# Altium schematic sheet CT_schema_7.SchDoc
size 277 x 170 mm
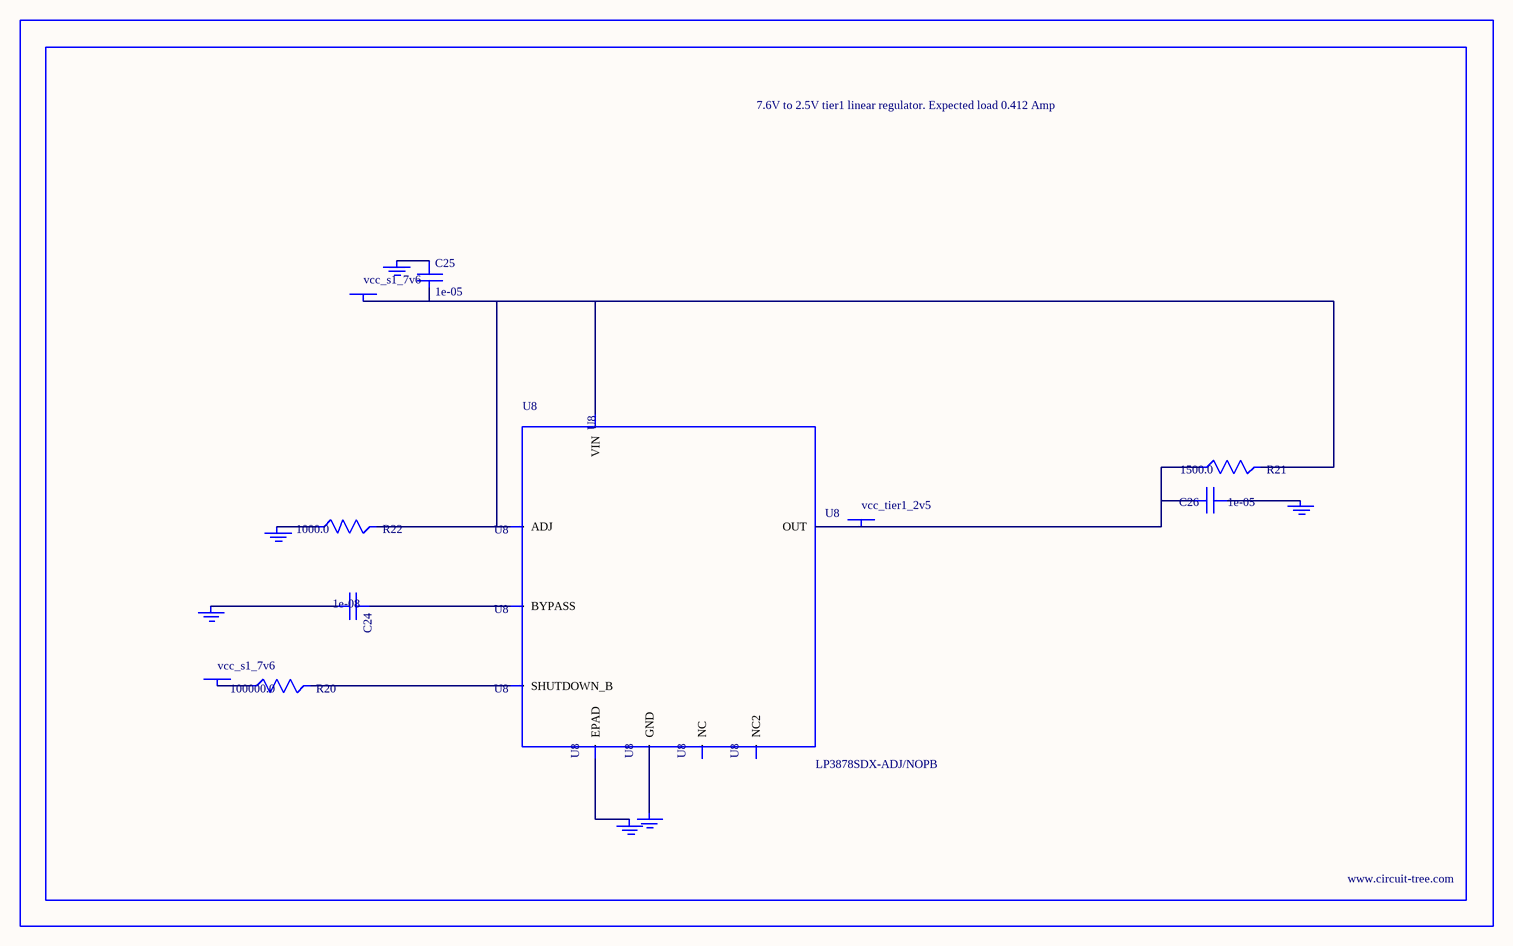
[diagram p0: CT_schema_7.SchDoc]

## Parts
BORDER6  (no value)
C24  1e-08  [C0402]
C25  1e-05  [C1206]
C26  1e-05  [C1210]
GND_INSTANCE_6_0  (no value)
GND_INSTANCE_6_1  (no value)
GND_INSTANCE_6_2  (no value)
GND_INSTANCE_6_3  (no value)
GND_INSTANCE_6_4  (no value)
GND_INSTANCE_6_5  (no value)
POWER_INSTANCE_6_0  vcc_s1_7v6
POWER_INSTANCE_6_1  vcc_s1_7v6
POWER_INSTANCE_6_2  vcc_tier1_2v5
R20  100000.0  [R0603]
R21  1500.0  [R0603]
R22  1000.0  [R0603]
U8  LP3878SDX-ADJ/NOPB  [WSON-8]

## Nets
NetC24_1: C24.1 U8.1(BYPASS)
NetC24_2: C24.2 GND_INSTANCE_6_0.0(GND)
NetC25_1: C25.1 GND_INSTANCE_6_1.0(GND)
NetC25_2: C25.2 POWER_INSTANCE_6_0.0(PWR) R21.2 R22.2 U8.4(VIN) U8.6(ADJ)
NetC26_1: C26.1 GND_INSTANCE_6_2.0(GND)
NetC26_2: C26.2 POWER_INSTANCE_6_2.0(PWR) R21.1 U8.5(OUT)
NetGND_INSTANCE_6_3_0: GND_INSTANCE_6_3.0(GND) R22.1
NetGND_INSTANCE_6_4_0: GND_INSTANCE_6_4.0(GND) U8.PAD(EPAD)
NetGND_INSTANCE_6_5_0: GND_INSTANCE_6_5.0(GND) U8.3(GND)
NetPOWER_INSTANCE_6_1_0: POWER_INSTANCE_6_1.0(PWR) R20.1
NetR20_2: R20.2 U8.8(SHUTDOWN_B)

Not connected (* = marked no-connect by the designer): U8 2(NC) 7(NC2)

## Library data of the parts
BORDER6 = BORDER_PAGE6
C24 = C0402C103K3RAC
C25 = C1206C106K3RACTU
C26 = GRM32DR61E106MA12L
GND_INSTANCE_6_0-GND_INSTANCE_6_5 = GND
POWER_INSTANCE_6_0-POWER_INSTANCE_6_2 = PWR
R20 = RC0603JR-07100KL
R21 = RC0603JR-071K5L
R22 = RC0603JR-071KL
